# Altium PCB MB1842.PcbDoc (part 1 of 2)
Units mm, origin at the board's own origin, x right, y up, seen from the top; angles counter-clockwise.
Board outline 64.57 x 35 mm, 4 copper layers (Top Layer, MidLayer 1, MidLayer 2, Bottom Layer), stack 1.066 mm thick; 81 components, 72 nets, 272 pads, 1151 vias.
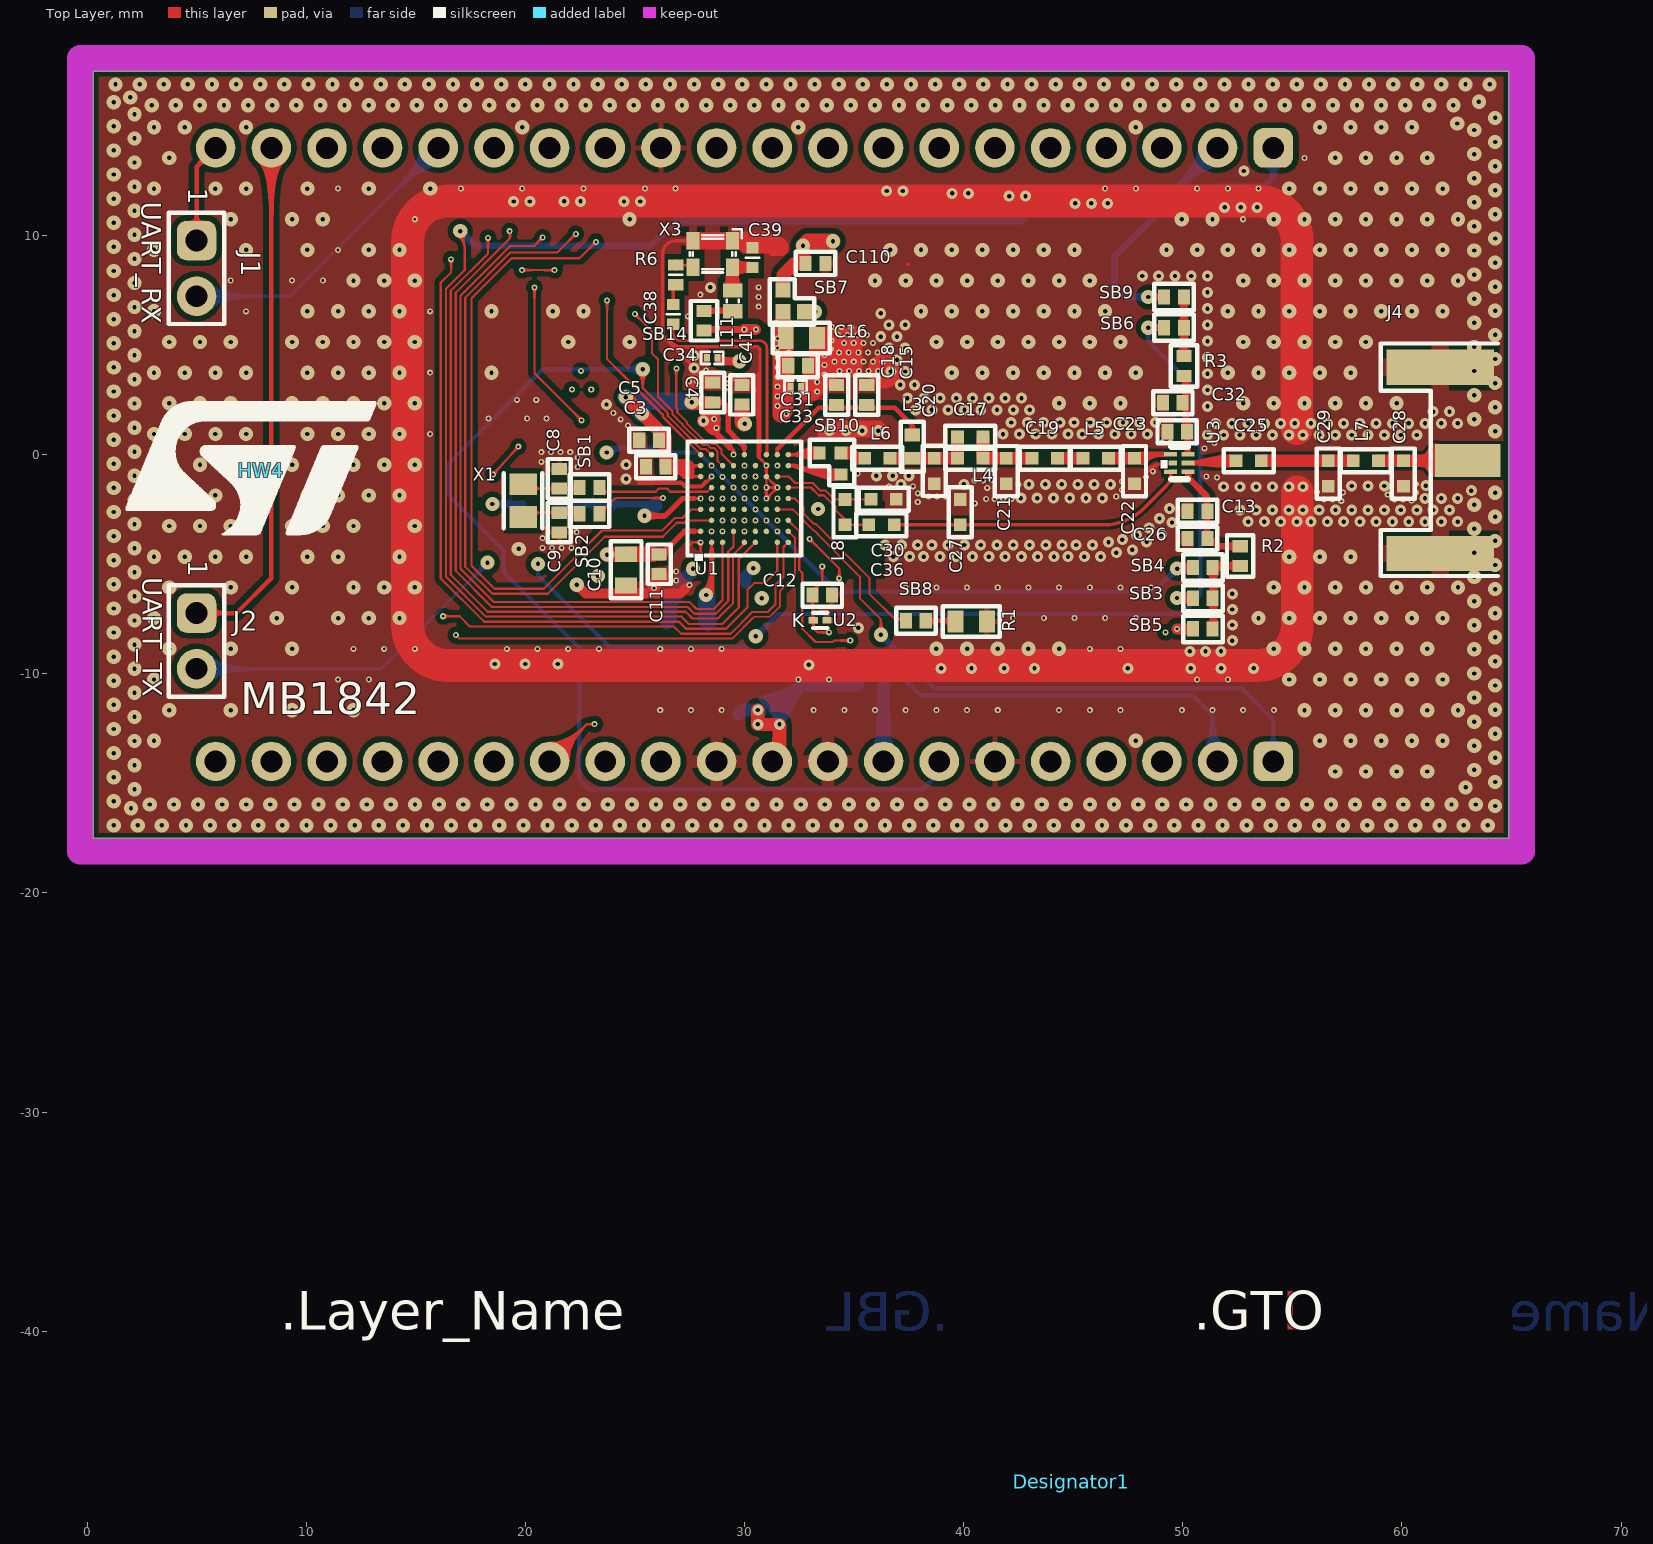
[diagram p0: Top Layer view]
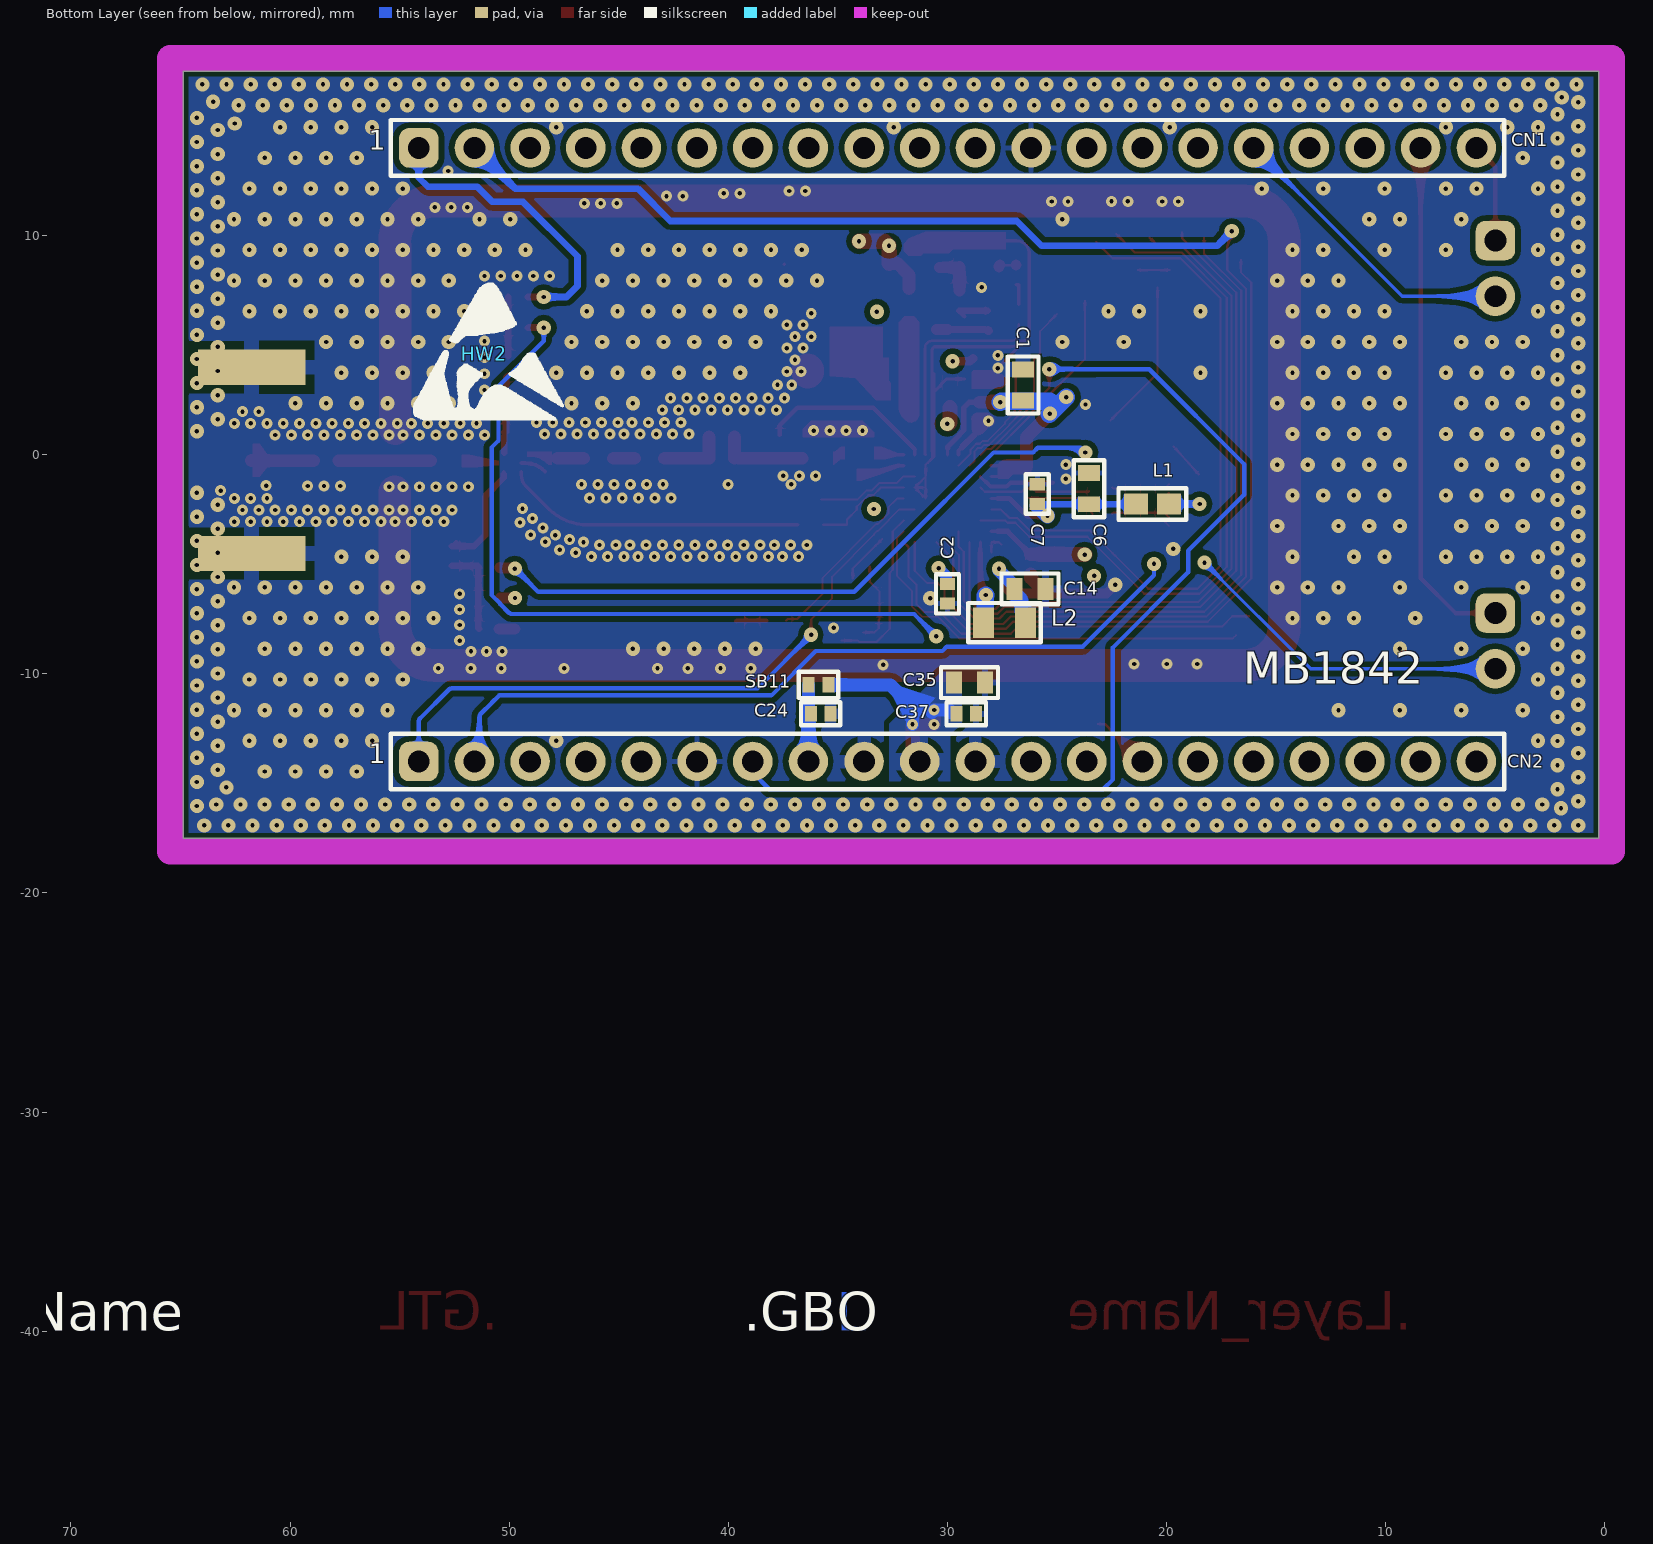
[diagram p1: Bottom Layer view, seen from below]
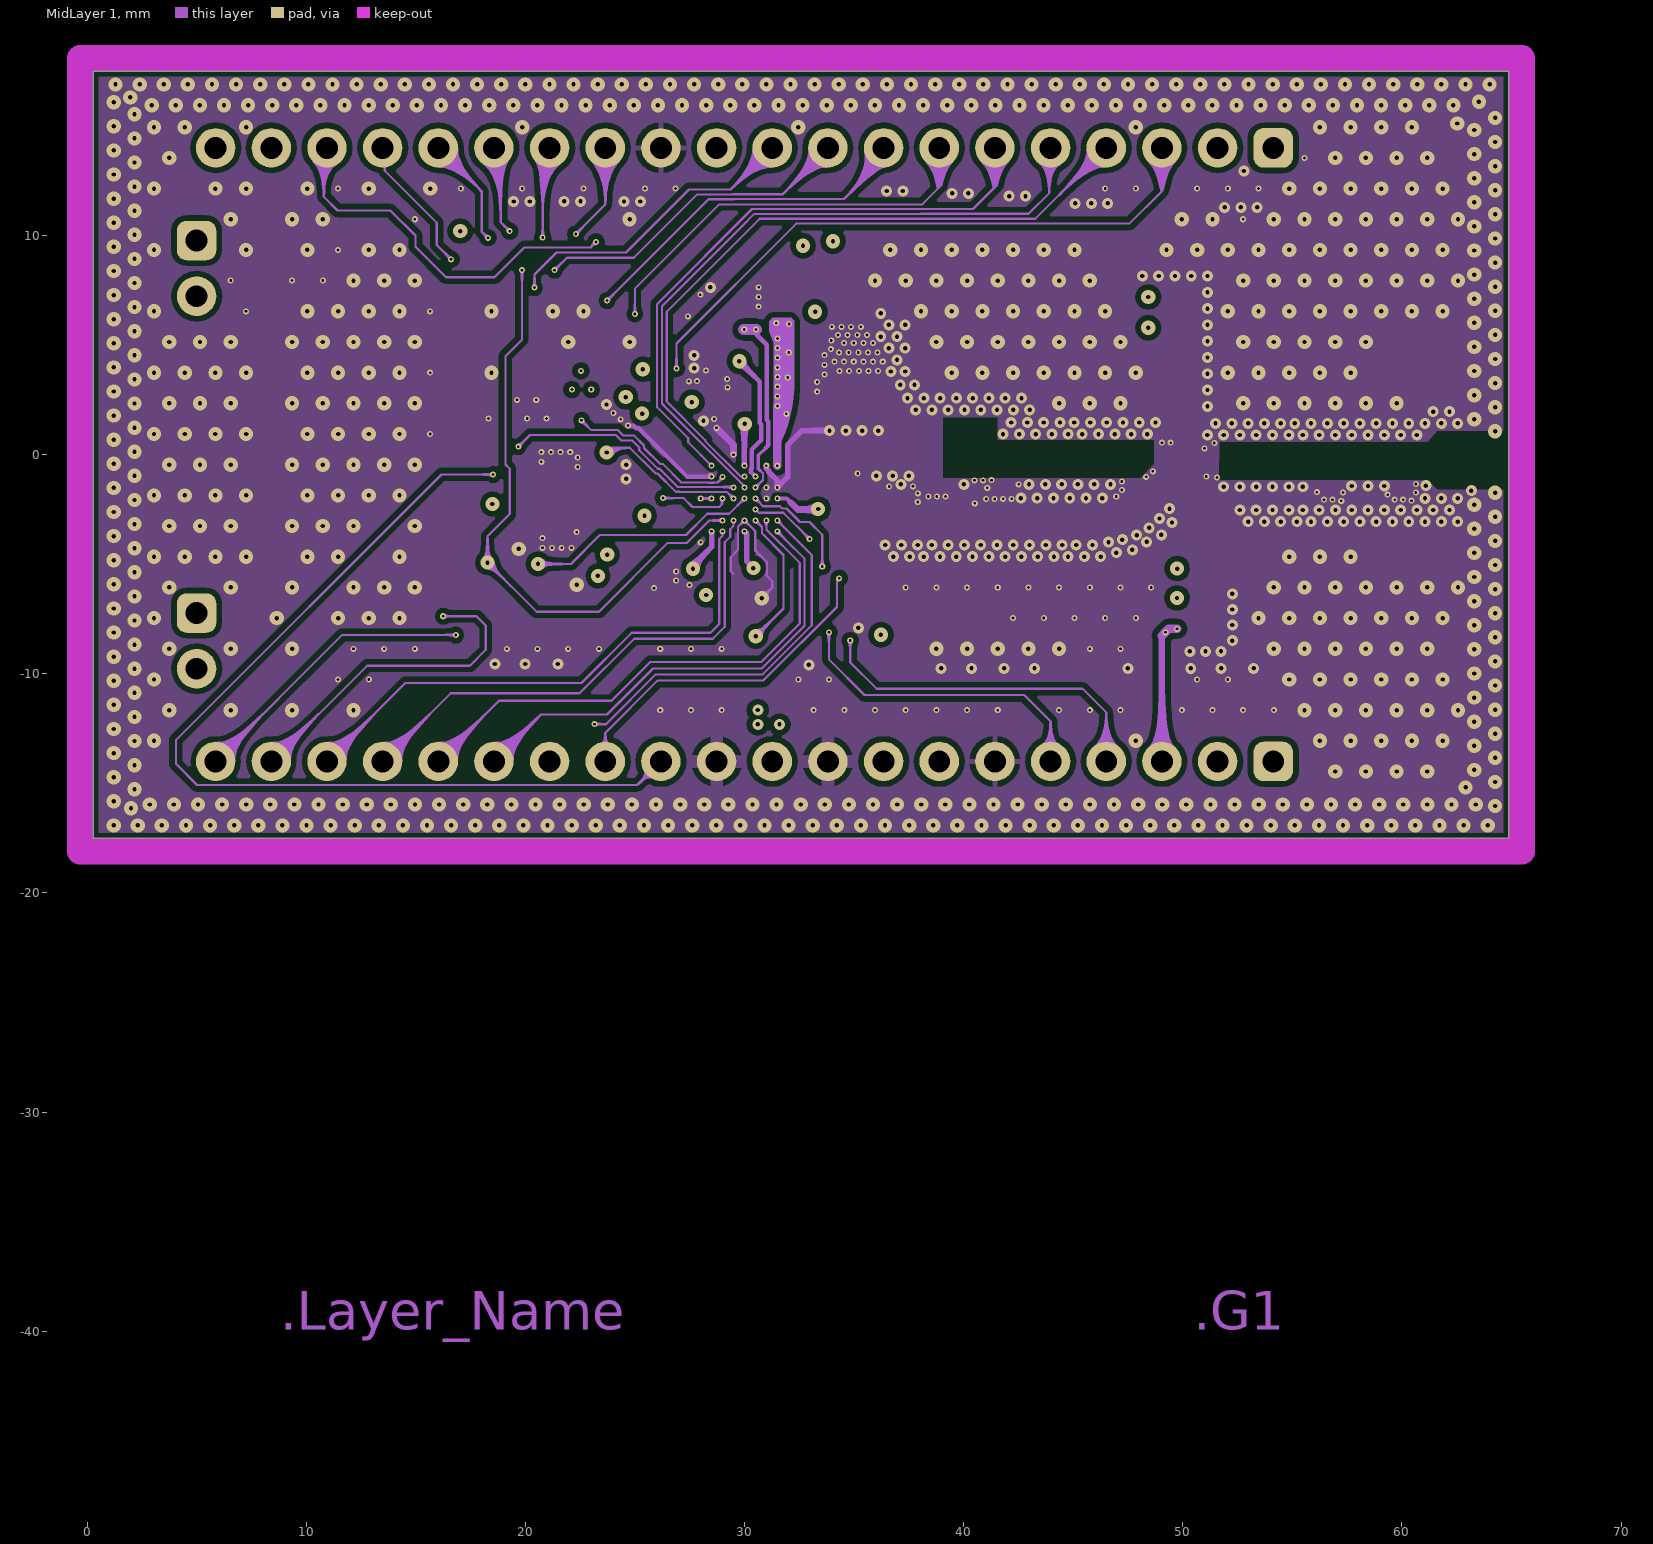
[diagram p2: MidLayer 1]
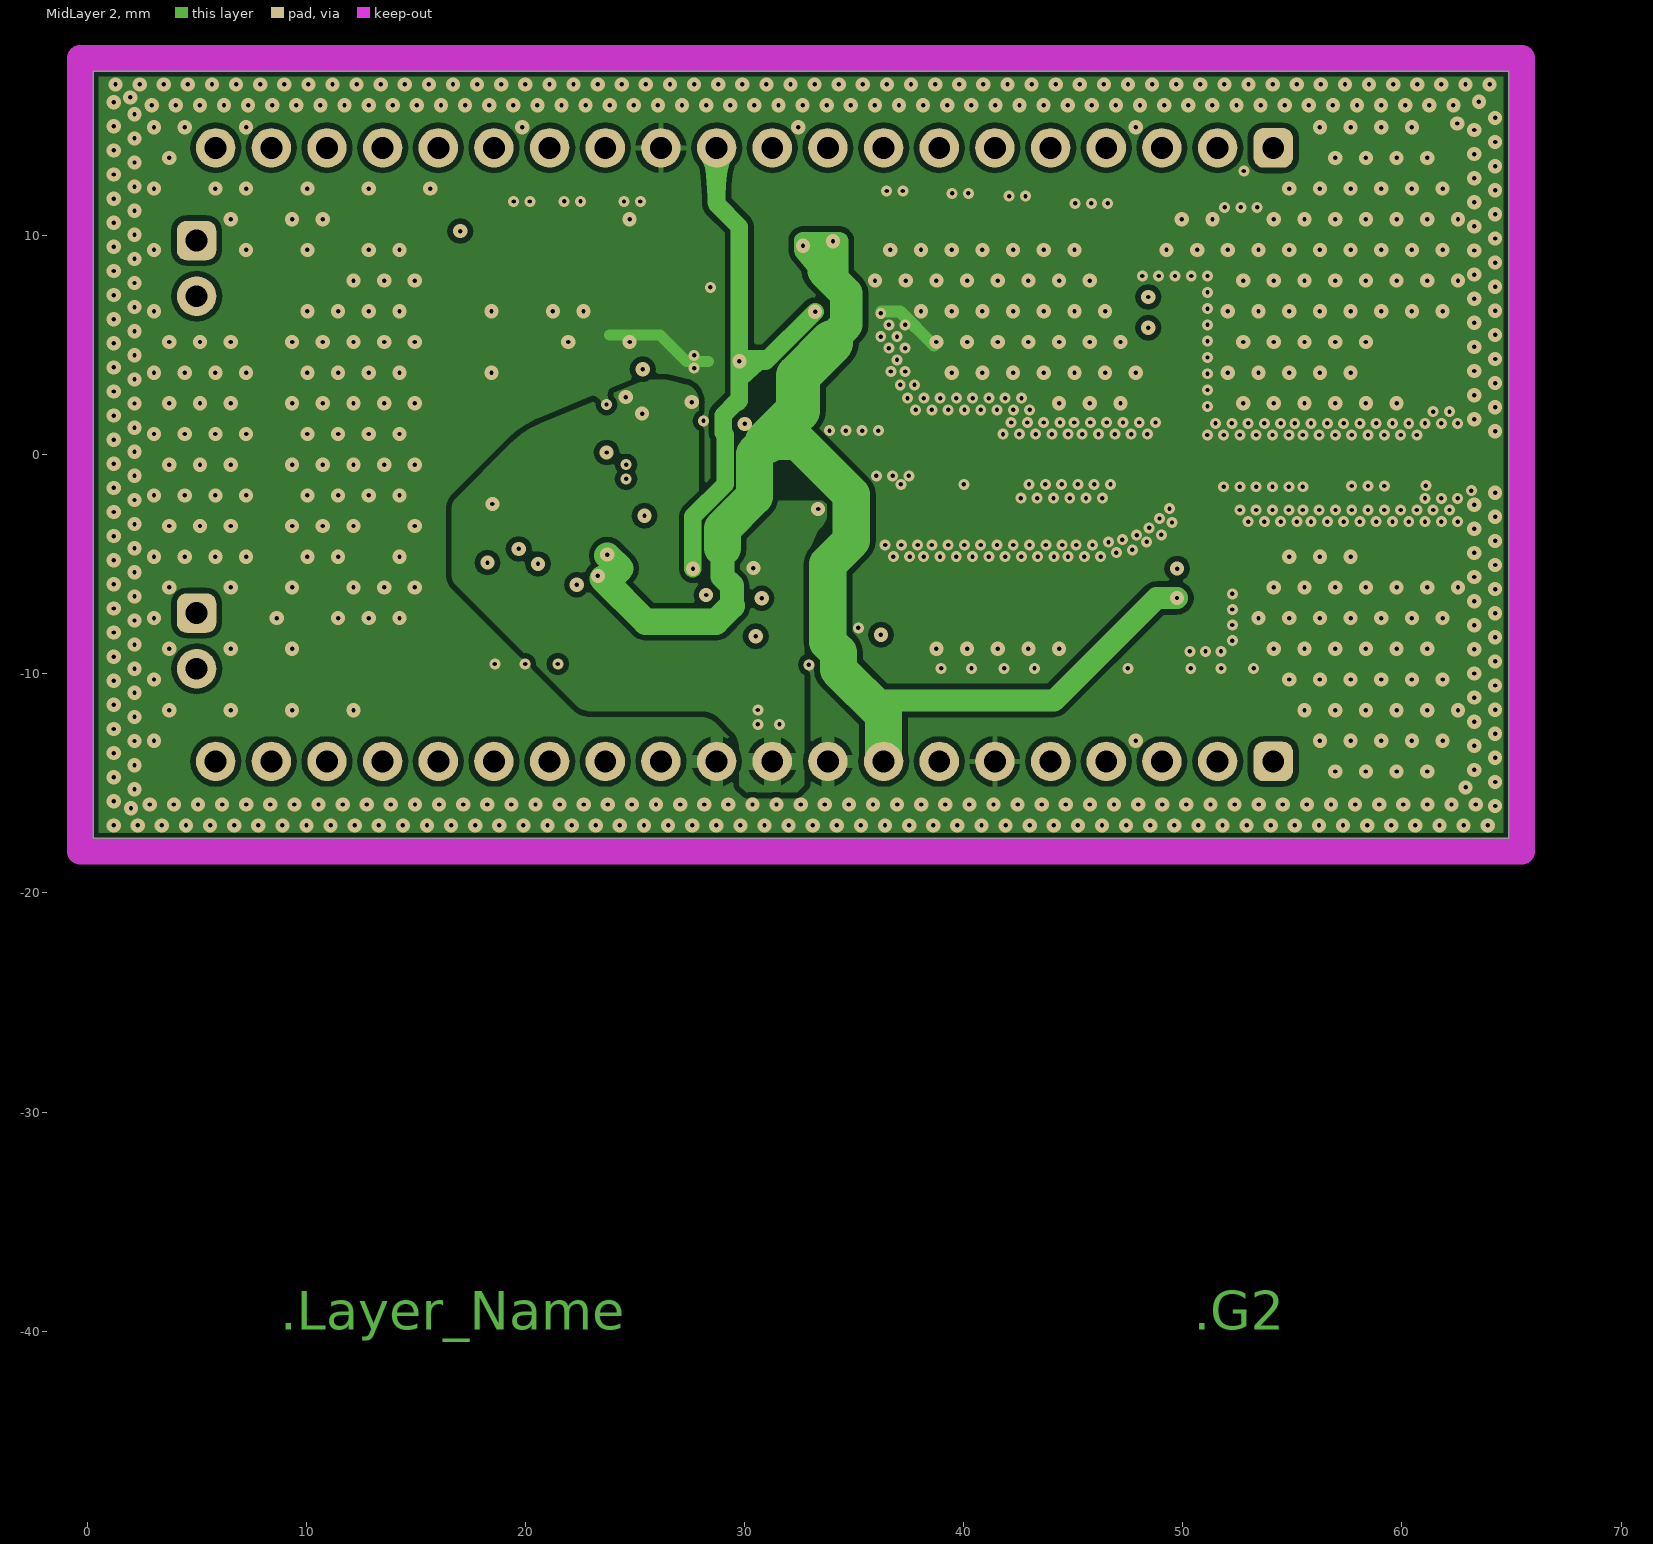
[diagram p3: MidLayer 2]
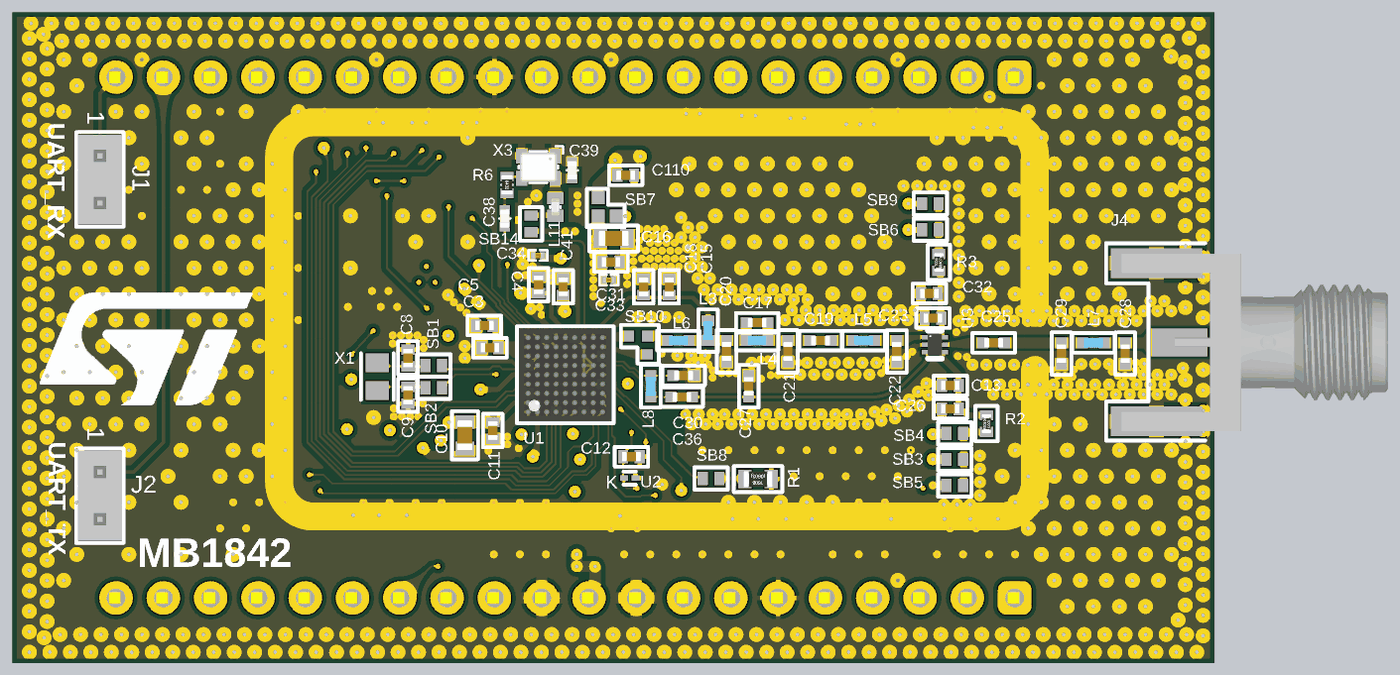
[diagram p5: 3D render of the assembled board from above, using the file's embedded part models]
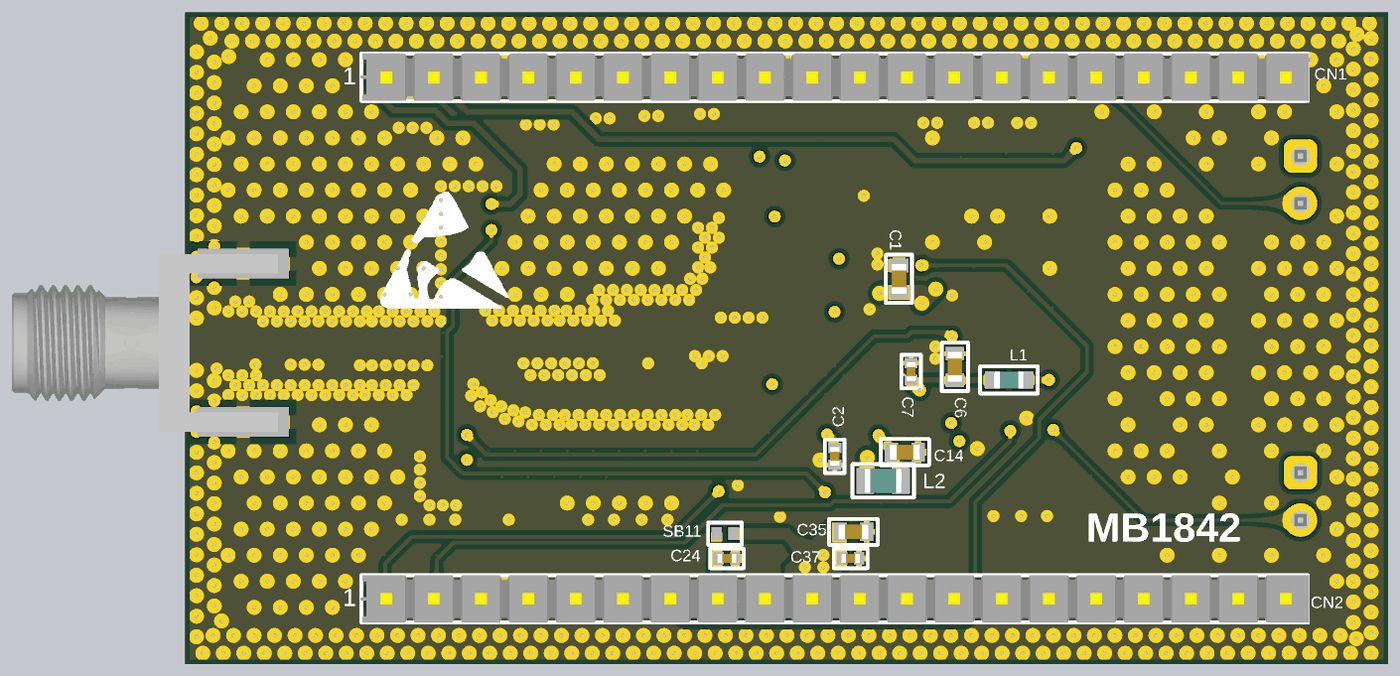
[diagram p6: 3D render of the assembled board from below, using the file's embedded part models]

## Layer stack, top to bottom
Top Solder: solder mask 0.0508, Solder Resist, Dk 3.7
Top Layer: signal copper 0.035
Dielectric 1: prepreg 0.108, 1 x 2116, Dk 3.8
MidLayer 1: signal copper 0.035
Dielectric 2: core 0.71, FR4, Dk 5
MidLayer 2: signal copper 0.035
Dielectric 3: prepreg 0.108, 1 x 2116, Dk 3.8
Bottom Layer: signal copper 0.035
Bottom Solder: solder mask 0.0508, Solder Resist, Dk 3.7

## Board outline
0.296,-17.511 0.296,17.489 64.868,17.489 64.868,-17.511

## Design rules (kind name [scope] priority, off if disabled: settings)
BoardOutlineClearance [All] p1 off: gap=0.6 ignorepadtopadclearanceinfootprint=FALSE
Clearance Clearance_RF_Polygon [InNetClass('50Ohms') vs InPolygon] p1: gap=0.15 ignorepadtopadclearanceinfootprint=TRUE except(0.14: Arc-Fill Arc-Poly Arc-Region Track-Fill Track-Poly Track-Region)
Clearance PairDiff [InNet('RFI_N') vs InNet('RFI_P')] p2: gap=0.1 ignorepadtopadclearanceinfootprint=TRUE
Clearance Clearance_1 [OnLayer('MidLayer 1')       and InPolygon vs All    and WithinRoom('RoomDefinition_BGA')] p3: gap=0.15 ignorepadtopadclearanceinfootprint=TRUE
Clearance Clearance_tab [(ObjectKind = 'Pad') And (Name Like 'Tab*-*') vs OnLayer('Keep-Out Layer')] p4: gap=0 ignorepadtopadclearanceinfootprint=TRUE
Clearance Clearance_Via_BGA [TouchesRoom('RoomDefinition_BGA') vs isvia or ispad or istrack] p5: gap=0.24 ignorepadtopadclearanceinfootprint=TRUE except(0.085: Arc-Arc Arc-SMDPad Arc-THPad Arc-Text Arc-Hole Track-SMDPad Track-THPad Track-Text Track-Hole SMDPad-SMDPad SMDPad-THPad SMDPad-Text SMDPad-Hole THPad-THPad THPad-Text THPad-Hole Via-Text Via-Hole Text-Text Text-Hole; 0.09: Track-Track Track-Via; 0.1: Track-Poly Track-Region; 0.11: Arc-Via SMDPad-Via THPad-Via Via-Via; 0.12: Arc-Track; 0.15: Arc-Region SMDPad-Region THPad-Region Via-Region Region-Region)
Clearance Clearance_Via_BGA_Inner [TouchesRoom('RoomDefinition_BGA') and (OnLayer('MidLayer 1')) vs isvia or ispad or istrack] p6: gap=0.25 ignorepadtopadclearanceinfootprint=TRUE except(0.075: Track-Track Track-Via; 0.085: Arc-Arc Arc-SMDPad Arc-THPad Arc-Text Arc-Hole Track-SMDPad Track-THPad Track-Text Track-Hole SMDPad-SMDPad SMDPad-THPad SMDPad-Text SMDPad-Hole THPad-THPad THPad-Text THPad-Hole Via-Text Via-Hole Text-Text Text-Hole; 0.11: Arc-Via SMDPad-Via THPad-Via Via-Via; 0.12: Arc-Track; 0.15: Arc-Region Track-Region SMDPad-Region THPad-Region Via-Region Region-Region)
Clearance Clearance_via_to_via [(ObjectKind = 'Via') And (Net <> 'GND') vs (ObjectKind = 'Via') And (Net <> 'GND')] p7: gap=0.65 ignorepadtopadclearanceinfootprint=TRUE
Clearance "Clearance_Polygon to All" [InPolygon] p8: gap=0.25 ignorepadtopadclearanceinfootprint=TRUE
Clearance [All] p9: gap=0.12 ignorepadtopadclearanceinfootprint=TRUE except(0.25: Arc-Via Track-Via SMDPad-Via THPad-Via Via-Fill Via-Poly Via-Region)
ComponentClearance [All] p1: gap=0 collisioncheckmode=3 verticalgap=0.1 showdistances=FALSE
DiffPairsRouting [InDifferentialPair('RFI')] p1: maxlimit=0.2 minlimit=0.111 mostfreqgap=0.111 toplayer_minwidth=0.1 toplayer_maxwidth=0.145 toplayer_prefwidth=0.1 midlayer1_minwidth=0.1 midlayer1_maxwidth=0.145 midlayer1_prefwidth=0.1 midlayer2_minwidth=0.1 midlayer2_maxwidth=0.145 midlayer2_prefwidth=0.1 bottomlayer_minwidth=0.1 bottomlayer_maxwidth=0.145 bottomlayer_prefwidth=0.1 maxuncoupledlength=12.7
HoleSize [All] p1: absolutevalues=TRUE maxlimit=10 minlimit=0.025 maxpercent=80.000 minpercent=20.000
MaximumViaCount [All] p1: limit=3
MinimumSolderMaskSliver [All] p1: minsoldermaskwidth=0.1
PlaneConnect [InNet('GND')] p1: planeconnectstyle=Relief reliefexpansion=0.508 reliefentries=4 reliefconductorwidth=0.21 reliefairgap=0.21
PolygonConnect PolygonConnect_RF [(ObjectKind = 'Pad')    and       TouchesRoom('Room_RF_Polygon_Spacing')] p1: connectstyle=Direct reliefconductorwidth=0.254 reliefentries=4 polygonreliefangle="90 Angle" airgapwidth=0.254
PolygonConnect PolygonConnect_J1 [(ObjectKind = 'Pad') And (Name = 'J1-2')] p2: connectstyle=Direct reliefconductorwidth=0.254 reliefentries=4 polygonreliefangle="90 Angle" airgapwidth=0.254
PolygonConnect PolygonConnect_All [All] p3: thpad.connectstyle=Relief thpad.reliefconductorwidth=0.25 thpad.reliefentries=4 thpad.polygonreliefangle="90 Angle" thpad.airgapwidth=0.25 smdpad.connectstyle=Relief smdpad.reliefconductorwidth=0.25 smdpad.reliefentries=4 smdpad.polygonreliefangle="90 Angle" smdpad.airgapwidth=0.25 via.connectstyle=Direct via.reliefconductorwidth=0.2 via.reliefentries=4 via.polygonreliefangle="90 Angle" via.airgapwidth=0.25
RoomDefinition RoomDefinition_BGA [False] p1: confinementstyle=ConfineIn formatcopy=TRUE lockcomponents=FALSE outline 27.671,0.75 32.622,0.75 32.622,-4.247 27.671,-4.247
RoutingLayers "RoutingLayers_90 Ohms" [InDifferentialPairClass('All Differential Pairs')] p1: top layer_v5=TRUE mid layer 1_v5=TRUE mid layer 2_v5=TRUE bottom layer_v5=TRUE
RoutingLayers [All] p2: top layer_v5=TRUE mid layer 1_v5=TRUE mid layer 2_v5=TRUE bottom layer_v5=TRUE
RoutingVias RoutingVias_BGA [InDrillLayerPair('Top Layer - MidLayer 1')] p1: holewidth=0.125 width=0.25 viastyle="Through Hole" minholewidth=0.125 minwidth=0.23 maxholewidth=0.125 maxwidth=0.27
RoutingVias [All] p2: holewidth=0.2 width=0.65 viastyle="Through Hole" minholewidth=0.1 minwidth=0.2 maxholewidth=0.2 maxwidth=0.65
ShortCircuit [(ObjectKind = 'Via') And (DrillPair = 'Top Layer - MidLayer 1') vs Ispad] p1: allowed=TRUE
SilkToSilkClearance [All] p1: silktosilkclearance=0.2
SilkToSolderMaskClearance [IsPad] p1: minsilkscreentomaskgap=0.2 clearancetoexposedcopper=TRUE
SolderMaskExpansion SolderMaskExpansion_VIA [IsVia] p1: expansion=-0.2 istentingtop=FALSE
SolderMaskExpansion [All] p2: expansion=0.075 istentingtop=FALSE
Width Width_BGA [OnLayer('Top Layer')      and WithinRoom('RoomDefinition_BGA')] p1: maxlimit=0.35 minlimit=0.075 preferedwidth=0.1 toplayer_minwidth=0.08 midlayer1_maxwidth=0.1 midlayer2_minwidth=0.09 midlayer2_maxwidth=0.1 bottomlayer_minwidth=0.09 bottomlayer_maxwidth=0.1 minimp=50.000000 maximp=50.000000 favimp=50.000000
Width Width_50Ohms [InNetClass('50Ohms')] p2: maxlimit=0.6 minlimit=0.161 preferedwidth=0.582
Width [All] p3: maxlimit=2 minlimit=0.075 preferedwidth=0.15 toplayer_minwidth=0.08 toplayer_maxwidth=1.5 midlayer1_maxwidth=1 midlayer2_minwidth=0.1 bottomlayer_minwidth=0.1 bottomlayer_maxwidth=1.5 minimp=50.000000 maximp=50.000000 favimp=50.000000
21 further rules are at their usual default settings.

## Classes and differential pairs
net class 50Ohms: NetC17_1 NetC17_2 NetC19_1 NetC22_2 NetC25_1 NetC25_2 NetC27_2 NetC28_1
differential pair RFI: +RFI_P -RFI_N

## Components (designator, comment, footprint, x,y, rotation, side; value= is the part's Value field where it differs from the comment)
C1 "" CAPC1608X09N 26.552,3.181 r270 bottom value=4.7uF
C2 "" CAPC1005X06N 30,-6.35 r90 bottom value=100nF
C3 "" CAPC1005X06N 25.95,-0.55 r0 top value=100nF
C4 "" CAPC1005X06N 28.559,2.834 r270 top value=100nF
C5 "" CAPC1005X06N 25.65,0.65 r0 top value=100nF
C6 "" CAPC1608X09N 23.55,-1.55 r90 bottom value=4.7uF
C7 "" CAPC1005X06N 25.9,-1.8 r90 bottom value=100nF
C8 "Capacitor" CAPC1005X06N 21.55,-1.1 r90 top value="5.1 pF"
C9 "Capacitor" CAPC1005X06N 21.55,-3.1 r270 top value="5.1 pF"
C10 "" CAPC1608X09N 24.604,-5.255 r270 top value=4.7uF
C11 "" CAPC1005X06N 26.104,-5.002 r270 top value=100nF
C12 "" CAPC1005X06N 33.55,-6.407 r0 top value=100nF
C13 "" CAPC1005X06N 50.675,-2.576 r0 top value=1nF
C14 "" CAPC1608X09N 26.237,-6.125 r180 bottom value=0.47uF
C15 "" CAPC1005X06N 35.581,2.722 r270 top value="68 pF"
C16 "" CAPC1608X09N 32.597,5.327 r0 top value=4.7uF
C17 "" CAPACITOR__0402__RF 40.3,0.801 r0 top
C18 "" CAPC1005X06N 34.204,2.722 r90 top value="47 nF"
C19 "" CAPACITOR__0402__RF 43.707,-0.164 r180 top value=68pF
C20 "" CAPACITOR__0402__RF 38.658,-0.743 r270 top
C21 "" CAPACITOR__0402__RF 41.951,-0.747 r90 top
C22 "" CAPACITOR__0402__RF 47.8,-0.747 r90 top
C23 "" CAPC1005X06N 49.748,1.044 r0 top value=1nF
C24 "" CAPC1005X06N 35.789,-11.83 r180 bottom value=100nF
C25 "" CAPACITOR__0402__RF 53.006,-0.283 r0 top value=68pF
C26 "" CAPC1005X06N 50.674,-3.826 r180 top value=100nF
C27 "NC" CAPACITOR__0402__RF 39.849,-2.622 r270 top
C28 "" CAPACITOR__0402__RF 60.069,-0.863 r270 top
C29 "" CAPACITOR__0402__RF 56.644,-0.863 r270 top
C30 "" CAPACITOR__0402__RF 36.351,-2.04 r180 top
C31 "" CAPC1005X06N 32.45,4.061 r0 top value=100nF
C32 "" CAPC1005X06N 49.548,2.369 r180 top value=100nF
C33 "" 0201 32.578,3.095 r180 top value=33pF
C34 "" 0201 28.286,4.419 r0 top value=33pF
C35 "" CAPC1608X09N 28.999,-10.404 r180 bottom value=4.7uF
C36 "" CAPACITOR__0402__RF 36.25,-3.2 r0 top
C37 "" CAPC1005X06N 29.146,-11.83 r180 bottom value=100nF
C38 "Capacitor" C0402 26.751,6.399 r270 top value=10pF
C39 "" C0402 30.369,8.991 r270 top value=10nF
C41 "" CAPC1005X06N 29.885,2.73 r90 top value=100nF
C110 "" CAPC1005X06N 33.239,8.726 r0 top value=100nF
CN1 "CON20" CO_SAMTEC_TSW-120-07-X-S 30,14 r180 bottom locked
CN2 "CON20" CO_SAMTEC_TSW-120-07-X-S 30,-14 r180 bottom locked
Designator1 "Comment" Sheetbox_4L2S -0.189,-52.211 r0 top
Designator1 "Comment" PCB_SPECIFICATIONS -0.48,25.098 r0 top
Designator16 "Comment" IMPEDANCE_TABLE -0.091,63.93 r0 top
HW2 "Logo" LOGO_MAIN 51.15,4.6 r180 bottom value="LOGO ESD"
HW4 "Logo" LOGO_ST 7.948,-0.704 r0 top value="LOGO ST"
J1 "HEADER_1X2_L" CO_MOLEX_22-03-2021 5,8.5 r270 top
J2 "HEADER_1X2_L" CO_MOLEX_22-03-2021 5,-8.5 r270 top
J4 "Amphenol_132430" SMA_AMPHENOL_50OHMS_EDGE_PCB 64.5,-0.261 r90 top
L1 "" INDC1608X95N 20.65,-2.25 r0 bottom value=600R@100MHz
L2 "" INDC2012X13N 27.401,-7.668 r0 bottom value=15uH
L3 "" IND_MURATA_LQW15A 37.66,0.367 r90 top value="47 nF"
L4 "" INDUCTOR__0402__RF 40.3,-0.164 r0 top
L5 "" INDUCTOR__0402__RF 46.031,-0.164 r0 top
L6 "" INDUCTOR__0402__RF 36.065,-0.163 r180 top
L7 "" INDUCTOR__0402__RF 58.357,-0.283 r0 top
L8 "" INDUCTOR__0402__RF 34.586,-2.62 r90 top
L11 "" IND_0402_MURATA_BLM15H_H0P5 29.463,7.019 r270 top value=1400R@1GHz
R1 "" RESC1608X05N 40.35,-7.609 r180 top value=10K
R2 "" RESC1005X04N 52.618,-4.628 r270 top value=100R
R3 "" RESC1005X04N 50.056,4.044 r90 top value=100R
R6 "Resistor" R0402 26.866,8.204 r270 top value=220R
SB1 "Close" SB_0402 22.931,-1.5 r180 top
SB2 "Close" SB_0402 22.931,-2.7 r180 top
SB3 "Close" SB_0402 50.917,-6.551 r0 top
SB4 "Open" SB_0402 50.917,-5.152 r0 top
SB5 "Open" SB_0402 50.917,-7.952 r0 top
SB6 "Close" SB_0402 49.6,5.794 r0 top value=0
SB7 "SB_3Pads" SB3PADS_0402 32.279,6.537 r0 top
SB8 "Close" SB_0402 37.822,-7.578 r180 top
SB9 "Open" SB_0402 49.6,7.195 r0 top
SB10 "SB_3Pads" SB3Pads_0402 34.15,-0.391 r0 top
SB11 "Open" SB_0402 35.889,-10.504 r180 bottom
SB14 "Close" SB_0402 28.157,6.11 r270 top value=0
U1 "" BGA73C50P9X9_500X500X60 30,-2 r90 top locked
U2 "" DIOM0603X03N 33.456,-7.557 r0 top
U3 "BGS12SN6" SON40P70X40-6N 49.848,-0.38 r0 top
X1 "XTAL_2_PINS" OSC_NDK_NX2012SA 19.9,-2.1 r90 top value=32.768KHz
X3 "" CRY_NDK_NT2016SB_4P 28.549,9.16 r180 top value=32MHz

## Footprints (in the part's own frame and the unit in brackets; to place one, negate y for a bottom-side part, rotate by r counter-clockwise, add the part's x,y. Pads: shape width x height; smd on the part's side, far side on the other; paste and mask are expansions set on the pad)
0201 [mm]
  rect 0.28x0.35 smd: 1(0,0) 2(0.48,0)
  silkscreen extent -0.27,-0.28 0.75,0.28, body extent -0.06,-0.15 0.54,0.15, height 0.3
BGA73C50P9X9_500X500X60 [mm] "BGA, 73-Leads, Body 5.00x5.00mmx0.60mm, Pitch 0.50mm"
  round 0.25 smd mask+0.05: A1(-2,2) A2(-1.5,2) A4(-0.5,2) A5(0,2) A7(1,2) A8(1.5,2) A9(2,2) B1(-2,1.5) B2(-1.5,1.5) B3(-1,1.5) B4(-0.5,1.5) B5(0,1.5) B6(0.5,1.5) B7(1,1.5) B8(1.5,1.5) B9(2,1.5) C1(-2,1) C2(-1.5,1) C3(-1,1) C4(-0.5,1) C5(0,1) C6(0.5,1) C7(1,1) C8(1.5,1) D2(-1.5,0.5) D3(-1,0.5) D4(-0.5,0.5) D5(0,0.5) D6(0.5,0.5) D7(1,0.5) D8(1.5,0.5) D9(2,0.5) E1(-2,0) E2(-1.5,0) E3(-1,0) E4(-0.5,0) E5(0,0) E6(0.5,0) E7(1,0) E8(1.5,0) E9(2,0) F1(-2,-0.5) F2(-1.5,-0.5) F3(-1,-0.5) F4(-0.5,-0.5) F5(0,-0.5) F6(0.5,-0.5) F7(1,-0.5) F8(1.5,-0.5) G2(-1.5,-1) G3(-1,-1) G4(-0.5,-1) G5(0,-1) G6(0.5,-1) G7(1,-1) G8(1.5,-1) G9(2,-1) H1(-2,-1.5) H2(-1.5,-1.5) H3(-1,-1.5) H4(-0.5,-1.5) H5(0,-1.5) H6(0.5,-1.5) H7(1,-1.5) H8(1.5,-1.5) H9(2,-1.5) J1(-2,-2) J2(-1.5,-2) J3(-1,-2) J5(0,-2) J6(0.5,-2) J8(1.5,-2) J9(2,-2)
  silkscreen extent -2.6,-2.6 2.6,2.6, body extent -2.5,-2.5 2.5,2.5, height 0.6
C0402 [mm]
  rect 0.51x0.56 smd mask+0.05: 1(-0.45,0) 2(0.45,0)
  silkscreen extent 0,-0.3 0,0.3, body extent -0.5,-0.31 0.5,0.31, height 0.4
CAPACITOR__0402__RF [mm] "Inductor 2-Leads,Body 1.10x0.70x0.60mm(max)"
  rect 0.582x0.582 smd: 1(-0.58,0) 2(0.58,0)
  silkscreen extent -1.14,-0.53 1.14,0.53, body extent -0.5,-0.25 0.5,0.25, height 0.6
CAPC1005X06N [mm] "Chip Capacitor, 2-Leads, Body 1.00x0.50x0.60mm (0402)"
  rect 0.55x0.7 smd: 1(-0.45,0) 2(0.45,0)
  silkscreen extent -0.9,-0.52 0.9,0.53, body extent -0.5,-0.25 0.5,0.25, height 0.6
CAPC1608X09N [mm] "Chip Capacitor, 2-Leads, Body 1.60x0.80x0.90mm (0603)"
  rect 0.725x1 smd: 1(-0.712,0) 2(0.712,0)
  Top Layer pour cut-out: -0.3,0.7 0.3,0.7 0.3,-0.7 -0.3,-0.7
  silkscreen extent -1.3,-0.7 1.3,0.7, body extent -0.8,-0.4 0.8,0.4, height 0.9
CO_MOLEX_22-03-2021 [mm]
  rrect50% 1.8x1.8 hole 1: 1(-1.27,0)
  round 1.8 hole 1: 2(1.27,0)
  silkscreen extent -2.54,-1.27 2.54,1.27, body extent -2.41,-1.18 2.41,1.18, height 10.79
CO_SAMTEC_TSW-120-07-X-S [mm] "Header, 20-Leads, 50.80x2.54x10.80mm, Pitch 2.54mm"
  rrect50% 1.8x1.8 hole 1: 1(-24.13,0)
  round 1.8 hole 1: 2(-21.59,0) 3(-19.05,0) 4(-16.51,0) 5(-13.97,0) 6(-11.43,0) 7(-8.89,0) 8(-6.35,0) 9(-3.81,0) 10(-1.27,0) 11(1.27,0) 12(3.81,0) 13(6.35,0) 14(8.89,0) 15(11.43,0) 16(13.97,0) 17(16.51,0) 18(19.05,0) 19(21.59,0) 20(24.13,0)
  silkscreen extent -25.4,-1.27 25.4,1.27, body extent -25.46,-1.27 25.46,1.27, height 8.38
CRY_NDK_NT2016SB_4P [mm] "MCD-01492"
  rect 0.6x0.8 smd mask+0.05: 1(-0.9,-0.6) 2(0.9,-0.6) 3(0.9,0.6) 4(-0.9,0.6)
  silkscreen extent -1.32,-1.12 1.05,0.85, body extent -1.05,-0.85 1.05,0.85, height 0.81
DIOM0603X03N [mm] "Molded Diode, 2-Leads, Body 0.60x0.30mm"
  rect 0.425x0.3 smd: 1(-0.312,0) 2(0.312,0)
  silkscreen extent -0.33,-0.35 0.33,0.35, body extent -0.32,-0.18 0.33,0.18, height 0.33
IMPEDANCE_TABLE [mm]
IND_0402_MURATA_BLM15H_H0P5 [mm]
  rect 0.65x0.9 smd mask+0.05: 1(-0.475,0) 2(0.475,0)
  silkscreen extent -0.05,-0.28 0.05,0.28, body extent -0.53,-0.28 0.52,0.28, height 0.55
IND_MURATA_LQW15A [mm]
  rect 0.582x0.7 smd: 1(-0.53,0) 2(0.53,0)
  silkscreen extent -1.14,-0.53 1.14,0.53, body extent -0.5,-0.3 0.5,0.3, height 0.51
INDC1608X95N [mm] "Chip Inductor, 2-Leads, Body 1.75x0.95x0.95mm (0603)"
  rect 1.1x0.95 smd: 1(-0.75,0) 2(0.75,0)
  silkscreen extent -1.55,-0.72 1.55,0.72, body extent -0.8,-0.48 0.8,0.47, height 0.8
INDC2012X13N [mm] "Chip Inductor, 2-Leads, Body 2.0x1.2x1.3 (0805)"
  rect 0.96x1.4 smd: 1(-0.952,0) 2(0.952,0)
  silkscreen extent -1.65,-0.9 1.65,0.9, body extent -1,-0.65 1,0.65, height 1.18
INDUCTOR__0402__RF [mm] "Inductor 2-Leads,Body 1.10x0.70x0.60mm(max)"
  rect 0.582x0.582 smd: 1(-0.58,0) 2(0.58,0)
  silkscreen extent -1.14,-0.53 1.14,0.53, body extent -0.5,-0.3 0.5,0.3, height 0.51
LOGO_MAIN [mm]
  silkscreen extent -3.24,-3.02 3.65,3.22
LOGO_ST [mm]
  silkscreen extent -6.18,-2.95 5.25,3.14
OSC_NDK_NX2012SA [mm] "Crystal, 2-Leads, Body 2.05x1.20x0.55mm (Tol:-/+0.05)"
  rect 1x1.25 smd: 1(-0.75,0) 2(0.75,0)
  silkscreen extent -1.25,-0.87 1.25,0.87, body extent -1.04,-0.63 1.03,0.63, height 0.55
PCB_SPECIFICATIONS [mm]
R0402 [mm]
  rect 0.51x0.7 smd mask+0.05: 1(-0.45,0) 2(0.45,0)
  silkscreen extent 0,-0.3 0,0.3, body extent -0.52,-0.31 0.52,0.31, height 0.4
RESC1005X04N [mm] "Chip Resistor, 2-Leads, Body 1.00x0.50mm (0402)"
  rect 0.55x0.7 smd: 1(-0.45,0) 2(0.45,0)
  silkscreen extent -0.95,-0.6 0.95,0.6, body extent -0.5,-0.25 0.5,0.25, height 0.35
RESC1608X05N [mm] "Chip Resistor, 2-Leads, Body 1.60x0.80mm (0603)"
  rect 0.725x1 smd: 1(-0.713,0) 2(0.713,0)
  Top Layer pour cut-out: -0.3,0.7 0.3,0.7 0.3,-0.7 -0.3,-0.7
  silkscreen extent -1.3,-0.7 1.3,0.7, body extent -0.77,-0.42 0.78,0.43, height 0.45
SB3PADS_0402 [mm] "Solder Bridge 0 Ohm (0402)"
  rect 0.7x0.7 smd: 1(0.466,-0.009) 2(-0.517,-0.009) 3(-0.517,0.974)
  silkscreen extent -1.13,-0.61 0.91,1.46, body extent -0.79,-0.05 -0.29,0.95, height 0.25
SB3Pads_0402 [mm] "Solder Bridge 0 Ohm (0402)"
  rect 0.582x0.55 smd: 1(0.255,-0.516)
  rect 0.582x0.582 smd: 2(0.255,0.467)
  rect 0.55x0.582 smd: 3(-0.728,0.467)
  silkscreen extent -1.17,-1.01 0.86,1.07, body extent 0.03,-0.49 0.53,0.51, height 0.25
SB_0402 [mm] "Solder Bridge 0 Ohm (0402)"
  rect 0.55x0.7 smd: 1(-0.45,0) 2(0.45,0)
  silkscreen extent -0.9,-0.6 0.9,0.6, body extent -0.5,-0.25 0.5,0.25, height 0.25
Sheetbox_4L2S [mil] "Sheetbox 4 layers / 2 silkscreens"
  round 20 on Mech16: 1(813.78,210.69) 1(2736.9,210.69)
SMA_AMPHENOL_50OHMS_EDGE_PCB [mm] "RF Connector, SMA End Launch Jack for 0.047 inch (1.19 mm thickness) PCB, 50 Ohm, Flat Tab Contact"
  rect 1.5x3 smd mask+0.05: 1(0,1.5)
  rect 1.6x4.9 smd mask+0.05: 2(-4.25,2.75) 2(4.25,2.75)
  rect 1.6x4.9 smd far side mask+0.05: 2(-4.25,2.75) 2(4.25,2.75)
  silkscreen extent -5.27,0.13 5.33,5.47, body extent -4.76,-9.65 4.76,4.62, height 4.09
SON40P70X40-6N [mm] "SON, 6-Leads, Body 1.10x0.70mm, Pitch 0.40mm"
  rect 0.6x0.225 smd: 1(-0.4,0.4) 2(-0.4,0) 3(-0.4,-0.4) 4(0.4,-0.4) 5(0.4,0) 6(0.4,0.4)
  silkscreen extent -0.38,-0.75 0.38,0.75, body extent -0.38,-0.58 0.38,0.58, height 0.4

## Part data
C1 C6 C10 C16 C35: library part MCD-00009, "Capacitor, MLCC, 4.7uF, 16V, X5R, 10%, 0603, T=0.8mm", Manufacturer=YAGEO, Manufacturer_Part_Number=CC0603KRX5R7BB475, Package=C0603
C2 C3 C4 C5 C7 C11 C12 C24 C26 C31 C32 C37 C41 C110: library part MCD-00102, "Capacitor, MLCC, 100nF, 16V, X7R, 10%, 0402, T=0,5mm", Manufacturer=YAGEO, Manufacturer_Part_Number=CC0402KRX7R7BB104, Package=C0402
C8 C9: library part MCD-00003, "Capacitor, MLCC, 5.1 pF, 50V, NPO, +-0.1pF, 0402, T=0.5mm", Manufacturer=YAGEO, Manufacturer_Part_Number=CC0402CRNPO9BN5R1
C13 C23: library part MCD-00198, "Capacitor, MLCC, 1nF, 16V, X7R, 10%, 0402, T=0.5mm", Manufacturer=YAGEO, Manufacturer_Part_Number=CC0402KRX7R7BB102
C14: library part MCD-00009, "Capacitor, MLCC, 4.7uF, 16V, X5R, 10%, 0603, T=0.8mm", Manufacturer=YAGEO, Manufacturer_Part_Number=CC0603KRX5R7BB474, Package=C0603
C15: library part MCD-01123, "Capacitor, MLCC,68pF, 50V, C0G, 1%, 0402, T=0.5mm", Manufacturer=MURATA, Manufacturer_Part_Number=GRM1555C1E680JA01
C17 C22: library part MCD-01123, "RF Capacitor"
C18: library part MCD-01123, "Capacitor, MLCC,47nF, 16V, X7R, 10%, 0402, T=0.5mm", Manufacturer=MURATA, Manufacturer_Part_Number=GRM155C71H473KE19
C19 C25: library part MCD-01123, "Capacitor, MLCC,68pF, 50V, C0G, 1%, 0402, T=0.5mm", Manufacturer=MURATA, Manufacturer_Part_Number=GRM1555C1H680JA01
C20 C28 C29: library part MCD-00102, "RF Capacitor", Package=C0402
C21: library part MCD-00015, "RF Capacitor"
C27: library part MCD-01123, Manufacturer="Not Fitted"
C30 C36: library part MCD-01123
C33 C34: library part MCD-00277, "Multilayer Ceramic Capacitors MLCC - SMD/SMT 0201 33pF 25volts C0G 5%", Manufacturer=MURATA, Manufacturer_Part_Number=GJM0335C1E330JB01D
C38: library part MCD-00015, "Capacitor, MLCC, 10pF, 50V, NPO, +/-5%, 0402, T=0,5mm", Manufacturer=YAGEO, Manufacturer_Part_Number=CC0402JRNPO9BN100, Package=C0402
C39: library part MCD-00011, "Capacitor, MLCC, 10nF, 16V, X7R, 10%, 0402, T=0.5mm", Manufacturer=YAGEO, Manufacturer_Part_Number=CC0402KRX7R7BB103, Package=C0402
CN1 CN2: "Connector right-angle, pitch 2.54mm, 20 contacts", Manufacturer=SAMTEC, Manufacturer_Part_Number=TSW-120-07-L-S
Designator16: library part MCD-00279
HW2: library part MCD-00627, "\"Hand\" ESD logo footprint for PCB"
HW4: library part MCD-00625, "\"STMicroelectronics\" logo footprint for PCB"
J1 J2: "Header 1x2 Through hole 2.54mm", Manufacturer=MOLEX, Manufacturer_Part_Number=22-03-2021
J4: library part SMA_thickness_1.19mm_AMPHENOL, "RF Connector, SMA End Launch Jack for 0.047 inch PCB, 50 Ohm, Flat Tab Contact", Manufacturer=AMPHENOL, Manufacturer_Part_Number=132430
L1: library part MCD-00047, "SMD Chip ferrite bead, 600R@100MHz +/-25%, 350mA, 500mohm DC, 0603, T=0.8mm", Manufacturer=TAI-TECH, Manufacturer_Part_Number=FCM1608KF-601T03
L2: library part MCD-01433, "MLZ2012 Multilayer Shielded Inductor 15µH, ±5%", Manufacturer=TDK, Manufacturer_Part_Number=MLZ2012M150W
L3: library part MCD-01330, "RF Inductor", Manufacturer=MURATA, Manufacturer_Part_Number=LQW15AN47NG00
L4 L5 L6 L7: library part MCD-01330, "RF Inductor"
L8: library part MCD-01330
L11: library part MCD-01610, "ferrite bead, 1400ohms at 1GHz, 250mA, 1.1ohms DC max", Manufacturer=MURATA, Manufacturer_Part_Number=BLM15HG102SN1#, Package=L0402
R1: library part MCD-00220, "Resistor,10K,0603,1%,1/10W", Manufacturer=YAGEO, Manufacturer_Part_Number=RC0603FR-0710KL
R2 R3: library part MCD-00119, "Resistor,100R,0402,1%,1/16W", Manufacturer=YAGEO, Manufacturer_Part_Number=RC0402FR-07100RL
R6: library part MCD-00427, "Resistor,220R,0402,1%,1/16W", Manufacturer=YAGEO, Manufacturer_Part_Number=RC0402FR-07220RL, Package=R0402
SB1 SB2 SB3 SB6 SB8 SB14: library part SB_0Ohm, "Solder Bridge 0R [0402] (Populated with 0 Ohm)", Manufacturer="Vishay / Dale", Manufacturer_Part_Number=RCS04020000Z0ED
SB4: library part SB_Open, "Solder Bridge Open [0402] (Unpopulated)", Manufacturer="NOT FITTED"
SB5 SB9 SB11: library part SB_Open, "Solder Bridge Open [0402] (Unpopulated)"
SB7 SB10: "Solder Bridge Open [0402] (Unpopulated)", Manufacturer="NOT FITTED"
U1: library part MCD-01435, "Multiprotocol Wireless 32-bit MCUwith LPWAN Sub-GHz radio solution", Manufacturer=STMICROELECTRONICS, Manufacturer_Part_Number=STM32WL55JCU6
U2: library part MCD-00170, "ESD protection 6V1", Manufacturer=STMICROELECTRONICS, Manufacturer_Part_Number=ESDALC6V1-1U2
U3: "DC switch - Ultra-Low  SPDT analog switch", Manufacturer=INFINEON
X1: library part MCD-01479, "Crystal 32.768kHz, 6pF, -+20PPM, R=80K, SMD", Manufacturer=NDK, Manufacturer_Part_Number="NX2012SA 32.768KHz EXS00A-MU00527"
X3: library part MCD-01492, "NT2016SA-32M-END4263A", Manufacturer=NDK, Package="2016 size"

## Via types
v1: diameter 0.65, hole 0.2, Top Layer to Bottom Layer, 646 vias
v2: diameter 0.275, hole 0.125, Top Layer to MidLayer 1, 261 vias
v3: diameter 0.5, hole 0.2, Top Layer to Bottom Layer, 244 vias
